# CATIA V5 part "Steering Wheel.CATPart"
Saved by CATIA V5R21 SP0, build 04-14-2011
Part number: Steering Wheel
Bounding box of the stored display mesh (mm): x -360.883 to 360.883, y -360.883 to 360.883, z 0 to 350
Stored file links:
  D:\CATIA V5R21 E-RESOURCES\CATIA-V5R21\catia-v5r21-prt\c16-catia-v5r20-prt\Revolute_Joint-(Fig 16-3)\Cat_V5R21_Steering Wheel.CATPart
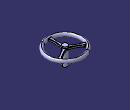
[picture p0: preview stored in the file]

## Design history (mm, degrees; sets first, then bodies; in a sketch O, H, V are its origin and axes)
Body1 (main body)
  Sketch1 on xy-plane, origin (0, 0, 0), H (1, 0, 0), V (0, 1, 0)
    circle A1 centre (0, 0) radius 50
    radius A1 = 50
  Pad1: profile Sketch1, direction (0, 0, 1), length 350
  Plane1: type Offset, RefPlane end face of Pad1, Offset 50
  Sketch2 on Plane1, origin (0, 0, 300), H (1, 0, 0), V (0, -1, 0)
    arc A1 centre (-620.9475, 180) radius 600 from (-40, 30) to (-40, 330) ccw
    point P1 (-620.9475, 180)
    point P2 (-40, 30)
    point P3 (-40, 330)
    reference projected circle E1 centre (0, 0) radius 50 from edge [start face of Pad1 | face of Pad1 from Sketch1.A1]
    construction line L1 (-40, 30) -> (-40, 330)
    point P4 (40, 330)
    point P5 (40, 30)
    arc A2 centre (620.9475, 180) radius 600 from (40, 30) to (40, 330) cw
    line L2 (-40, 30) -> (40, 30)
    line L3 (-40, 330) -> (40, 330)
    radius A1 = 600
    length L1 = 300
    distance H P1 = 180
    coincidence: P2 E1
    vertical: L1 V
    symmetry: P3 P4 V, P2 P5 V, A1 A2 V
    horizontal: L2 H, L3 H
  Pad2: profile Sketch2, direction (0, 0, -1), length 20, mirrored extent
  Fillet1: radius 7, on edge [start face of Pad2 | face of Pad2 from Sketch2.A1]; edge [face of Pad2 from Sketch2.A1 | end face of Pad2]; edge [face of Pad2 from Sketch2.A2 | end face of Pad2]; edge [start face of Pad2 | face of Pad2 from Sketch2.A2]; edge [face of Pad2 from Sketch2.A2 | face of Pad1 from Sketch1.A1]; edge [end face of Pad2 | face of Pad1 from Sketch1.A1]; edge [face of Pad1 from Sketch1.A1 | face of Pad2 from Sketch2.A1]; edge [face of Pad1 from Sketch1.A1 | start face of Pad2]
  CircPattern1: of Pad2, instances 3, angular step 120 {= 360.0*1 deg/CircPattern1.AngularNumber}, axis from face of Pad1 from Sketch1.A1
  Fillet2: radius 7, on edge [face of CircPattern1 | face of CircPattern1] (x2); face of CircPattern1 (x10)
  Sketch3 on yz-plane, origin (0, 0, 0), H (0, 1, 0), V (0, 0, 1)
    point P1 (-330, 300)
    ellipse A1 centre (-330, 300) semi-axes 37.5, 30.9839 rotation 90
    reference projected line E1 (-330, 320) -> (-330, 280) from edge [face of Pad2 from Sketch2.L3 | face of Pad2 from Sketch2.A2]
    reference projected line E2 (-49.5784, 320) -> (-330, 320) from edge [start face of Pad2 | face of Fillet1]
    distance P1 E2 = 20
    "Radius" A1 = 37.5
    coincidence: P1 E1
  Shaft1: profile Sketch3, axis axis of face of Pad1 from Sketch1.A1, angle 360
  Fillet3: radius 7, on face of Shaft1 from Sketch3.A1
